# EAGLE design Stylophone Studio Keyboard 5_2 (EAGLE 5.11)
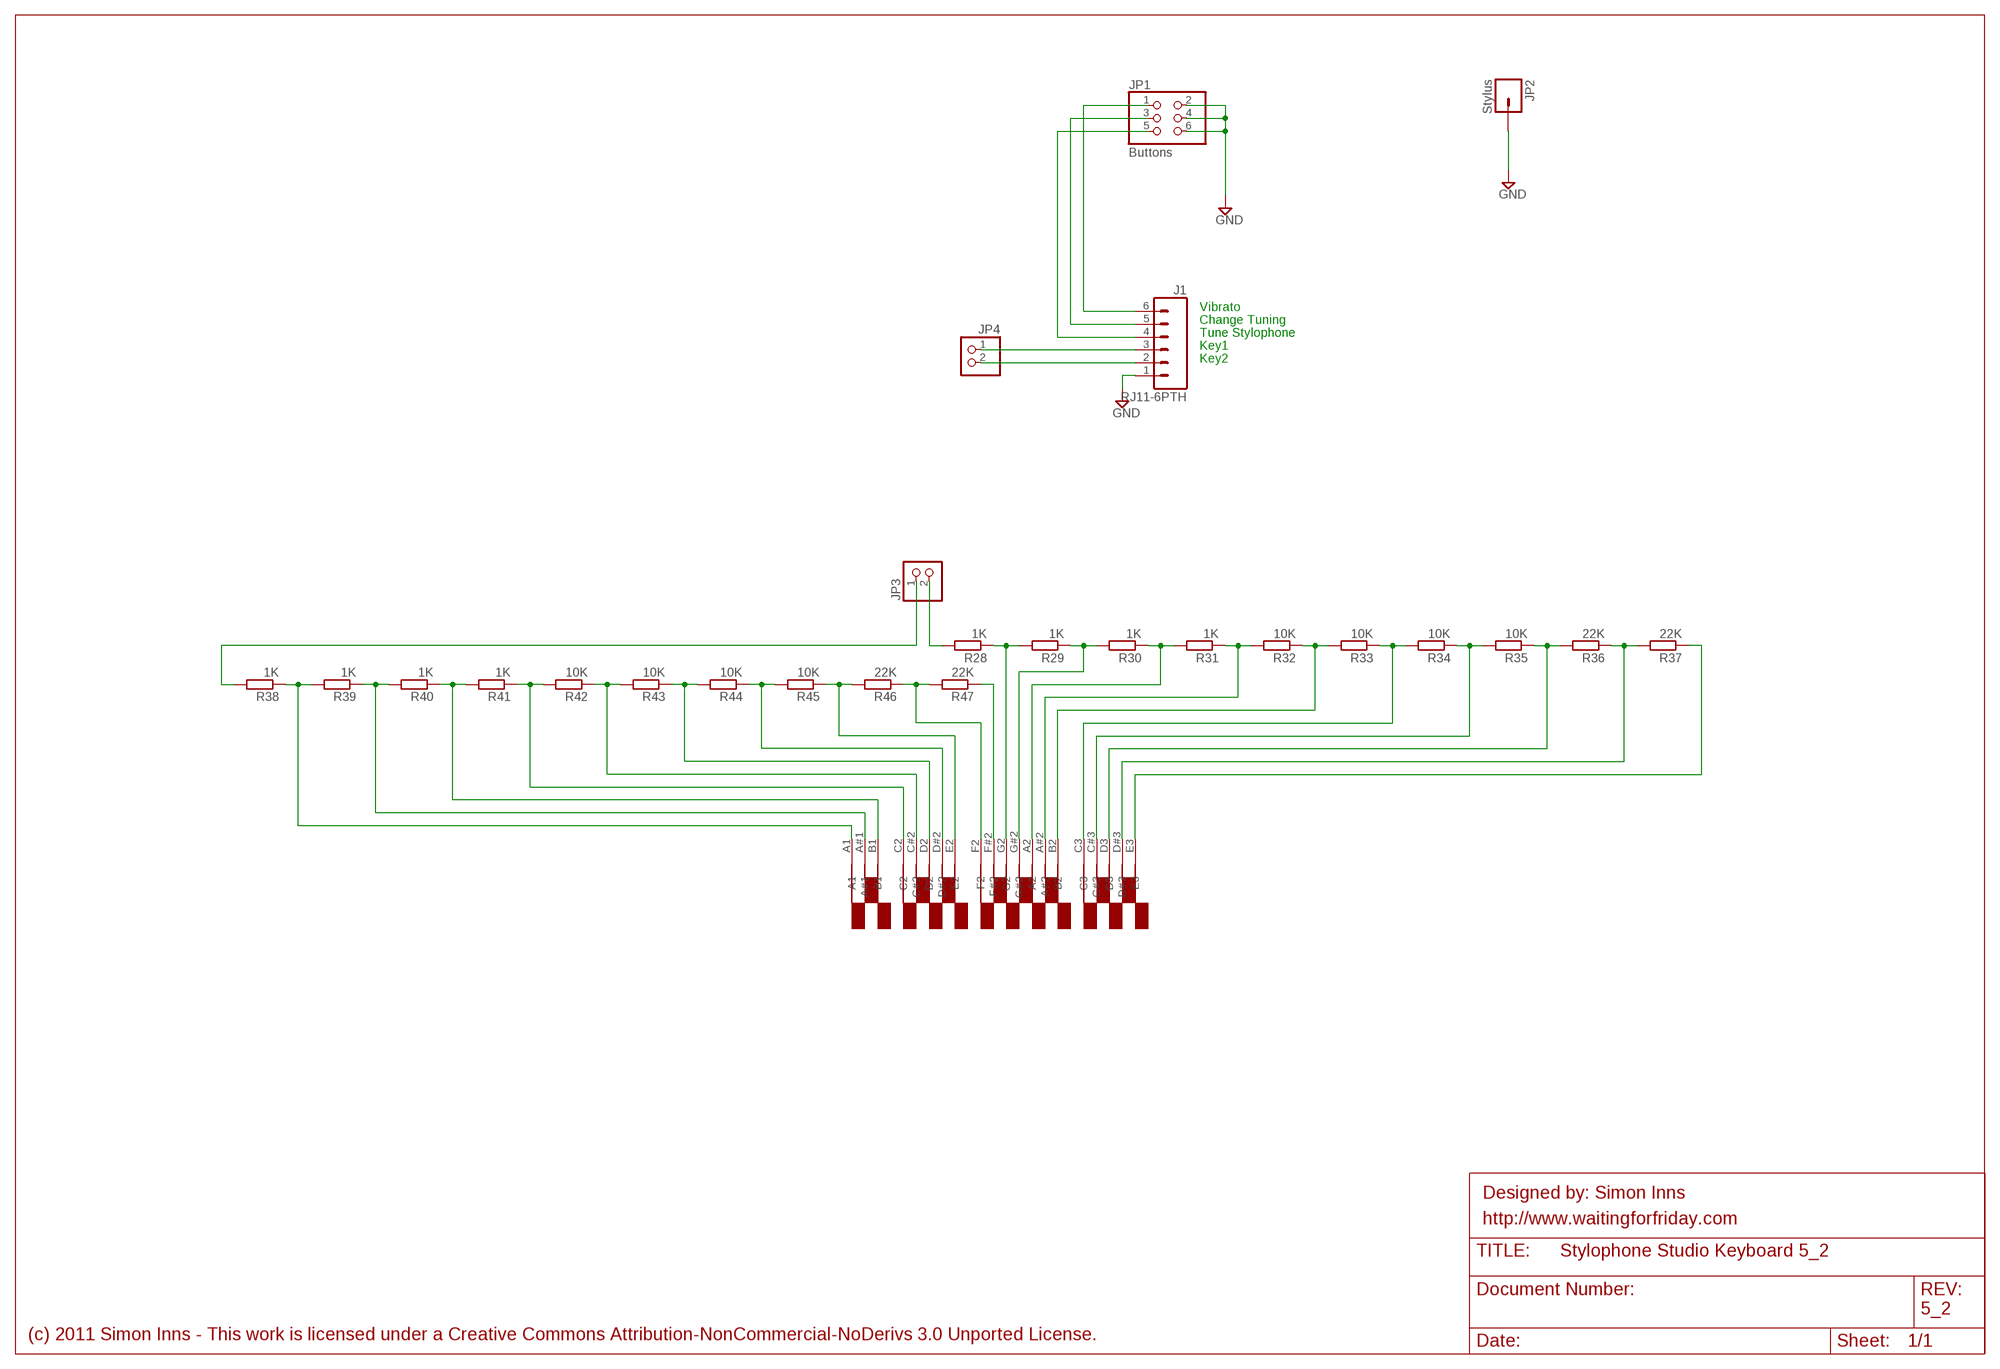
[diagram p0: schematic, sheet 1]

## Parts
J1  RJ11-6PTH  [RJ11-6]
JP1  Buttons  PINHD-2X3  [2X03]
JP2  Stylus  M01PTH  [1X01]
JP3  PINHD-1X2/90  [1X02/90]
JP4  PINHD-1X2/90  [1X02/90]
R28  1K  R-EU_M1206  [M1206]
R29  1K  R-EU_M1206  [M1206]
R30  1K  R-EU_M1206  [M1206]
R31  1K  R-EU_M1206  [M1206]
R32  10K  R-EU_M1206  [M1206]
R33  10K  R-EU_M1206  [M1206]
R34  10K  R-EU_M1206  [M1206]
R35  10K  R-EU_M1206  [M1206]
R36  22K  R-EU_M1206  [M1206]
R37  22K  R-EU_M1206  [M1206]
R38  1K  R-EU_M1206  [M1206]
R39  1K  R-EU_M1206  [M1206]
R40  1K  R-EU_M1206  [M1206]
R41  1K  R-EU_M1206  [M1206]
R42  10K  R-EU_M1206  [M1206]
R43  10K  R-EU_M1206  [M1206]
R44  10K  R-EU_M1206  [M1206]
R45  10K  R-EU_M1206  [M1206]
R46  22K  R-EU_M1206  [M1206]
R47  22K  R-EU_M1206  [M1206]
U$7  STYLOPHONE_KEYPAD_DEV  [STYLOPHONE_KEYBOARD_PACK]

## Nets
GND: J1.1 JP1.2 JP1.4 JP1.6 JP2.1
N$1: JP3.2 R28.2
N$2: JP3.1 R38.2
N$3: J1.6 JP1.1
N$4: J1.5 JP1.3
N$5: R47.1 U$7.F#2
N$6: J1.4 JP1.5
N$7: J1.3 JP4.1
N$8: J1.2 JP4.2
N$11: R28.1 R29.2 U$7.G2
N$17: R46.1 R47.2 U$7.F2
N$18: R45.1 R46.2 U$7.E2
N$21: R44.1 R45.2 U$7.D#2
N$22: R43.1 R44.2 U$7.D2
N$23: R42.1 R43.2 U$7.C#2
N$24: R41.1 R42.2 U$7.C2
N$25: R40.1 R41.2 U$7.B1
N$26: R39.1 R40.2 U$7.A#1
N$27: R37.1 U$7.E3
N$28: R38.1 R39.2 U$7.A1
N$29: R29.1 R30.2 U$7.G#2
N$43: R30.1 R31.2 U$7.A2
N$44: R31.1 R32.2 U$7.A#2
N$45: R32.1 R33.2 U$7.B2
N$46: R33.1 R34.2 U$7.C3
N$47: R34.1 R35.2 U$7.C#3
N$51: R35.1 R36.2 U$7.D3
N$52: R36.1 R37.2 U$7.D#3

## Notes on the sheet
- Vibrato
- Change Tuning
- Tune Stylophone
- Key1
- Key2
- Designed by: Simon Inns
- http://www.waitingforfriday.com
- 5_2
- (c) 2011 Simon Inns - This work is licensed under a Creative Commons Attribution-NonCommercial-NoDerivs 3.0 Unported License.

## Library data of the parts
J1 = SparkFun:RJ11-6: RJ11 Jack Simple 6 pin RJ11 jack. Commonly found on CAT3 devices and Microchip programmers. SKU: PRT-00132
JP1 = pinhead:PINHD-2X3: PIN HEADER
JP2 = SparkFun:M01: Header 1
JP3 JP4 = pinhead:PINHD-1X2: PIN HEADER
R28-R47 = rcl:R-EU_: RESISTOR, European symbol
U$7 = simonslbr:STYLOPHONE_KEYPAD_DEV: Dubreq 1968 Stylophone Keypad

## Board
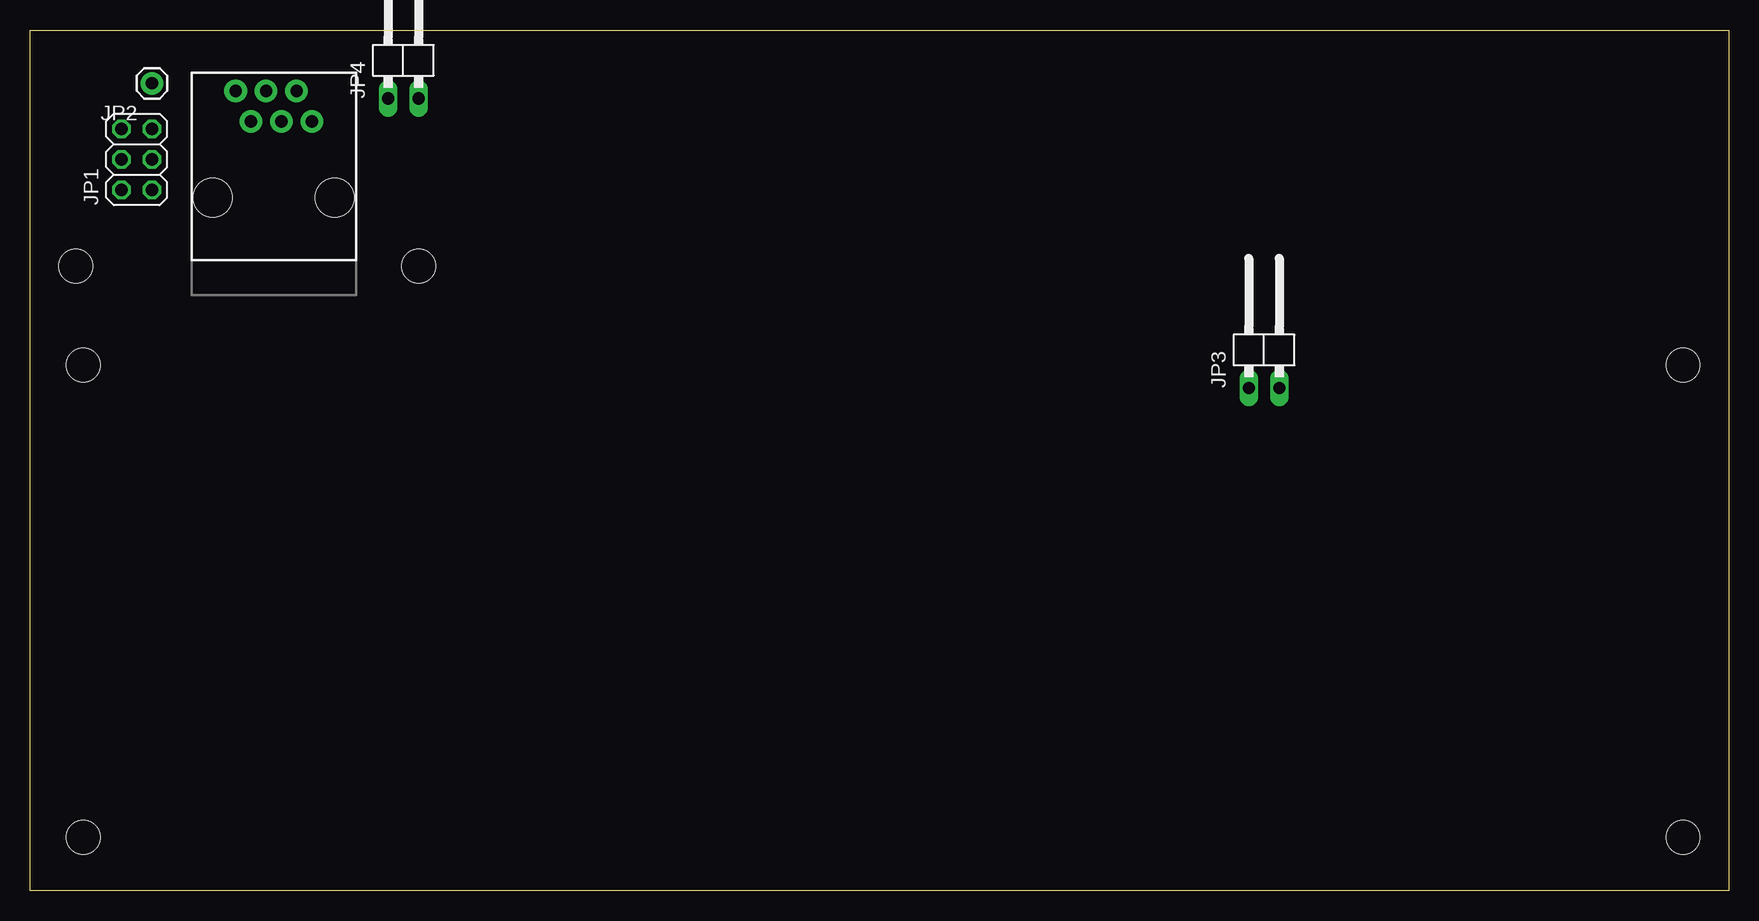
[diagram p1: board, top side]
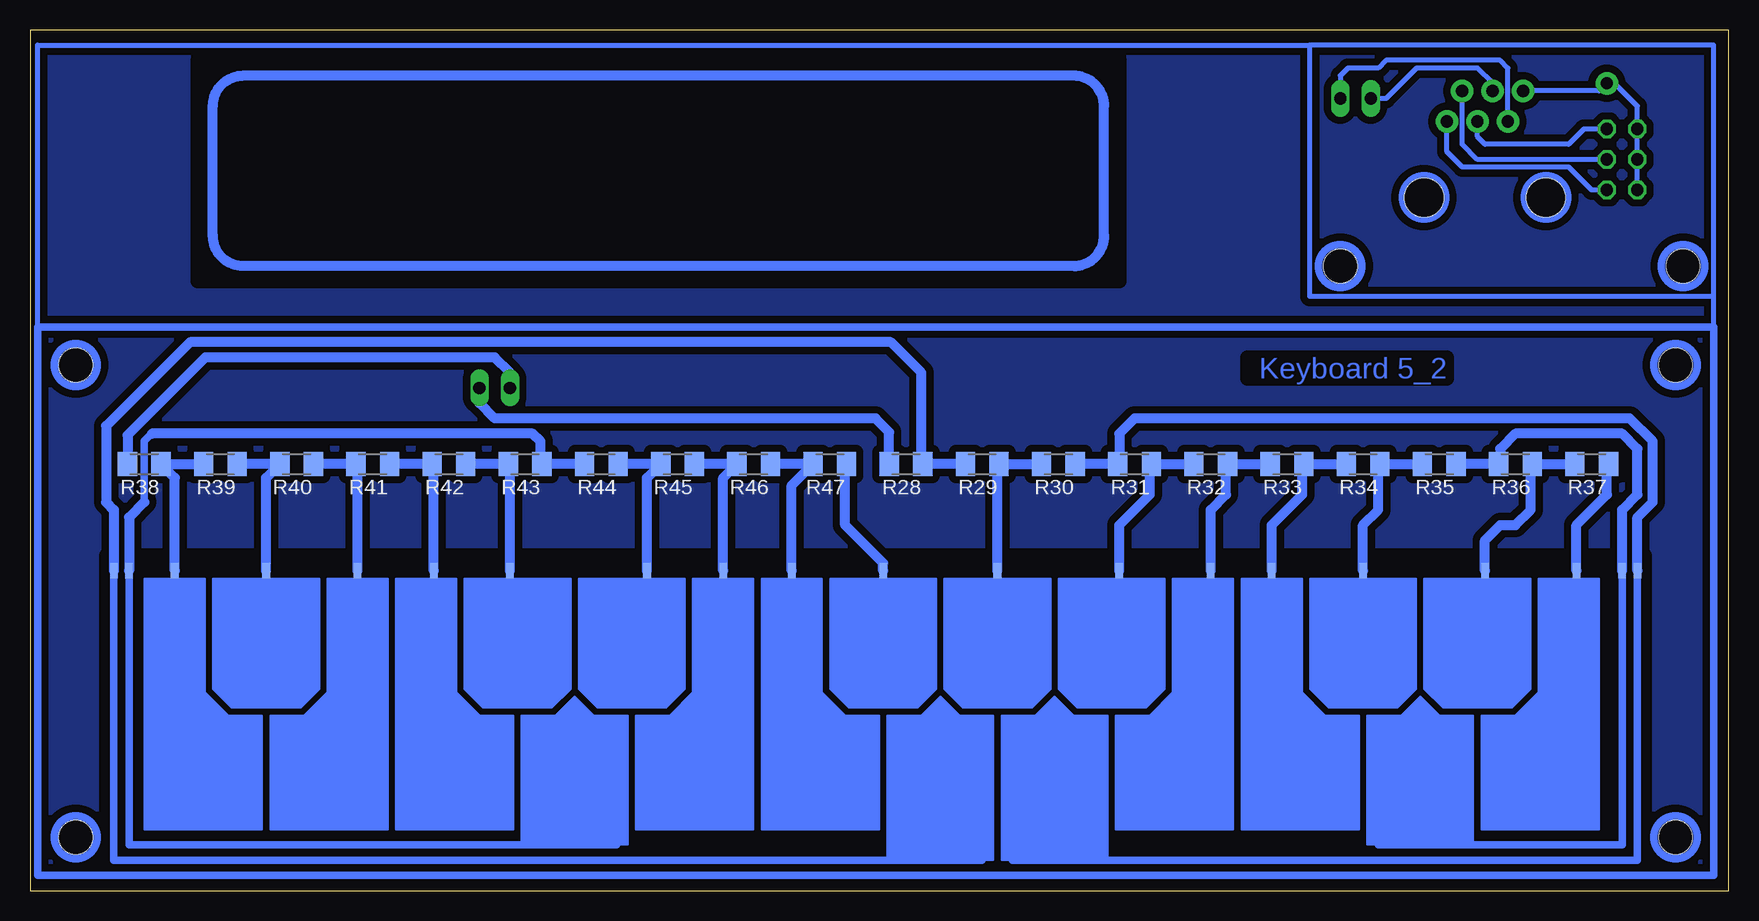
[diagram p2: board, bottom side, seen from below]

Size 141.6 x 71.75 mm. Coordinates in mm from the lower left corner, seen from the top.
Outline: 0,0 0,71.75 141.6,71.75 141.6,0 0,0
Copper layers (1*16): Top 0.035mm / dielectric 1.5mm / Bottom 0.035mm
Design rules "default": minimum track width 10mil, minimum drill 24mil, track to track 8mil, track to pad 8mil, pad to pad 8mil, via to via 8mil, smd to smd 8mil, copper to edge 40mil, drill to drill 8mil, minimum pad ring 10mil, minimum via ring 8mil, stop-mask expansion 4mil, vias tented up to drill 0mil, thermal gap 10mil
Holes 2.8 mm at 137.79,4.45 4.45,4.45 137.79,43.81 4.45,43.81 32.38,52.07 3.81,52.07
bRestrict: area 7,1.9 to 135.3,27.9; area 50.8,50.8 to 127.6,69.2

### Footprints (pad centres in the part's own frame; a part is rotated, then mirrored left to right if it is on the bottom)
RJ11-6 = drill 1.016 pad 1.88 round: 1 1.905,8.89; 2 3.175,6.35; 3 4.445,8.89; 4 5.715,6.35; 5 6.985,8.89; 6 8.255,6.35 | hole 3.251: 0,0; 10.16,0
2X03 = drill 1.016 octagon: 1 -2.54,-1.27; 2 -2.54,1.27; 3 0,-1.27; 4 0,1.27; 5 2.54,-1.27; 6 2.54,1.27
1X01 = drill 1.016 pad 1.88 round: 1 0,0
1X02/90 = drill 1.016 long: 1 -1.27,-3.81; 2 1.27,-3.81
M1206 = smd 1.6 x 2: 1 -1.4,0; 2 1.4,0
STYLOPHONE_KEYBOARD_PACK = smd 0.635 x 1.27: A1 5.08,24.13; A2 127,24.13; A#1 12.7,24.13; A#2 83.82,24.13; B1 20.32,24.13; B2 91.44,24.13; C2 26.67,24.13; C3 96.52,24.13; C#2 33.02,24.13; C#3 104.14,24.13; D2 1.27,24.13; D3 125.73,24.13; D#2 44.45,24.13; D#3 114.3,24.13; E2 50.8,24.13; E3 121.92,24.13; F2 56.515,24.13; F#2 64.135,24.13; G2 0,24.13; G#2 73.66,24.13

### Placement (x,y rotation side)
J1  15.24,57.78 0 top
JP1  8.89,60.96 90 top
JP2  10.16,67.31 180 top
JP3  102.87,45.72 0 top
JP4  31.11,69.85 0 top
R28  68.58,35.56 180 bottom
R29  62.23,35.56 180 bottom
R30  55.88,35.56 180 bottom
R31  49.53,35.56 180 bottom
R32  43.18,35.56 180 bottom
R33  36.83,35.56 180 bottom
R34  30.48,35.56 180 bottom
R35  24.13,35.56 180 bottom
R36  17.78,35.56 180 bottom
R37  11.43,35.56 180 bottom
R38  132.08,35.56 180 bottom
R39  125.73,35.56 180 bottom
R40  119.38,35.56 180 bottom
R41  113.03,35.56 180 bottom
R42  106.68,35.56 180 bottom
R43  100.33,35.56 180 bottom
R44  93.98,35.56 180 bottom
R45  87.63,35.56 180 bottom
R46  81.28,35.56 180 bottom
R47  74.93,35.56 180 bottom
U$7  134.62,2.54 0 bottom

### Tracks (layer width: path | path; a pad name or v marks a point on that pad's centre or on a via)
GND
  Bottom 0.406: J1.1 10.79,66.67 JP2.1 9.53,67.31 7.62,65.41 JP1.6 JP1.4 JP1.2
N$1
  Bottom 0.813: R28.2 69.98,38.23 71.12,39.37 102.87,39.37 104.14,40.64 JP3.2
N$2
  Bottom 0.813: R38.2 133.48,37.97 127,44.45 102.87,44.45 101.6,43.18 JP3.1
N$3
  Bottom 0.406: J1.6 23.5,61.59 22.23,60.33 13.34,60.33 11.43,58.42 JP1.1
N$4
  Bottom 0.406: J1.5 22.23,62.23 20.95,60.96 JP1.3
N$5
  Bottom 0.813: U$7.F#2 70.48,27.3 73.66,30.48 73.66,35.43 R47.1
N$6
  Bottom 0.406: J1.4 20.95,62.87 20.32,62.23 13.34,62.23 12.06,63.5 JP1.5
N$7
  Bottom 0.406: J1.3 19.68,67.31 20.95,68.58 26.04,68.58 28.57,66.04 JP4.1
N$8
  Bottom 0.406: J1.2 18.41,68.58 19.05,69.22 28.57,69.22 29.21,68.58 31.75,68.58 32.38,67.94 JP4.2
N$9
  pour Bottom (isolate 0.61): 1.27,70.48 140.97,70.48 140.97,1.27 1.27,1.27
N$10
  Bottom 0.406: 34.92,70.48 1.27,70.48 1.27,49.53 | 1.27,49.53 34.92,49.53 34.92,70.48 | 34.92,70.48 140.97,70.48 140.97,46.99 | 1.27,46.99 1.27,49.53
  Bottom 0.61: 1.27,1.27 140.97,1.27 140.97,46.99 1.27,46.99 1.27,1.27
N$11
  Bottom 0.813: R29.2 R28.1 | 134.62,31.75 U$7.G2 | 135.25,32.38 134.62,31.75 | R28.1 67.31,35.69 | 135.25,32.38 134.62,31.75 | 135.25,32.38 135.25,38.73 128.27,45.72 69.85,45.72 67.31,43.18 67.31,35.69 | R28.1 67.31,35.69
N$12
  Bottom 0.813: 54.61,67.94 123.19,67.94 123.83,67.94 arc-90 126.36,65.41 126.36,54.61 arc-90 123.83,52.07 123.19,52.07 54.61,52.07 arc-90 52.07,54.61 52.07,65.41 arc-90 54.61,67.94
N$17
  Bottom 0.813: U$7.F2 78.11,33.78 R47.2 R46.1
N$18
  Bottom 0.813: U$7.E2 83.82,34.42 R46.2 R45.1
N$21
  Bottom 0.813: U$7.D#2 90.17,34.42 R45.2 R44.1
N$22
  Bottom 0.61: 132.08,32.38 132.08,37.47 131.44,38.1
  Bottom 0.813: R44.2 R43.1 99.06,35.69 99.06,37.47 99.69,38.1 131.44,38.1 | U$7.D2 133.35,31.11 132.08,32.38
N$23
  Bottom 0.813: U$7.C#2 101.6,35.43 R43.2 R42.1
N$24
  Bottom 0.813: U$7.C2 107.95,35.43 R42.2 R41.1
N$25
  Bottom 0.813: U$7.B1 114.3,35.43 R41.2 R40.1
N$26
  Bottom 0.813: U$7.A#1 121.92,34.42 R40.2 R39.1
N$27
  Bottom 0.813: U$7.E3 12.7,30.48 10.16,33.02 10.16,35.43 R37.1
N$28
  Bottom 0.813: U$7.A1 129.54,34.42 R38.1 R39.2
N$29
  Bottom 0.813: U$7.G#2 60.96,35.43 R29.1 R30.2
N$43
  Bottom 0.813: U$7.A2 7.62,31.11 6.35,32.38 6.35,37.47 8.26,39.37 49.53,39.37 50.8,38.1 50.8,35.69 R31.2 R30.1
N$44
  Bottom 0.813: U$7.A#2 50.8,30.48 48.26,33.02 48.26,35.43 R31.1 R32.2
N$45
  Bottom 0.813: U$7.B2 43.18,31.75 41.91,33.02 41.91,35.43 R32.1 R33.2
N$46
  Bottom 0.813: U$7.C3 38.1,30.48 35.56,33.02 35.56,35.43 R33.1 R34.2
N$47
  Bottom 0.813: U$7.C#3 30.48,30.48 29.21,31.75 29.21,35.43 R34.1 R35.2
N$51
  Bottom 0.813: U$7.D3 8.89,31.75 7.62,33.02 7.62,36.83 8.89,38.1 17.78,38.1 19.05,36.83 19.05,35.69 R36.2 R35.1
N$52
  Bottom 0.813: U$7.D#3 20.32,29.21 19.05,30.48 17.78,30.48 16.51,31.75 16.51,35.43 R36.1 R37.2
(copper drawn outside any net)
  shapes: Bottom circle x8

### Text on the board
Bottom: Keyboard 5_2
